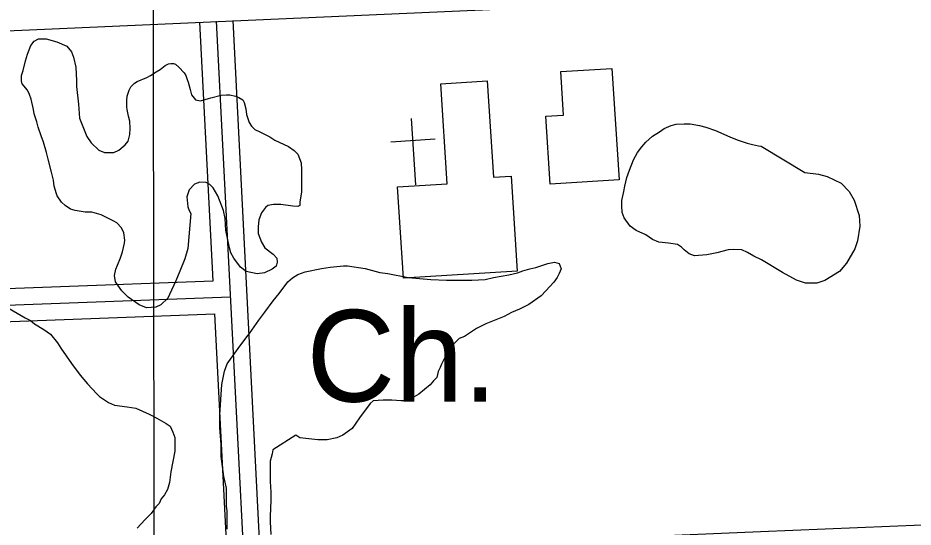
# Model space of a CAD drawing. Extents: x 3313442 to 3351311, y 721974 to 747360.
# Drawn here: x 3333194 to 3334005, y 732187 to 732648 of the extents above; entities that cross this region are included whole.
import ezdxf

# ---------------------------------------------------------------- set-up
doc = ezdxf.new("R2010")
doc.units = 0
for name, color, linetype in [('V-BLDG-OTLN', 7, 'Continuous'), ('V-GRID-MAJR', 7, 'Continuous'), ('V-ROAD-CNTR', 7, 'Continuous'), ('V-SITE-OTLN', 7, 'Continuous'), ('V-SITE-OTLN-IDEN', 7, 'Continuous'), ('V-SITE-VEGE', 7, 'Continuous')]:
    doc.layers.add(name, color=color, linetype=linetype)

msp = doc.modelspace()

# ---------------------------------------------------------------- linework, layer by layer
at = {"layer": 'V-BLDG-OTLN'}
for points in [[(3333731.8, 732602.58), (3333738.19, 732501.68), (3333675.78, 732497.73), (3333671.89, 732559.28), (3333687.97, 732560.29), (3333685.48, 732599.65)], [(3333618.92, 732591.21), (3333624.4, 732504.01), (3333640.54, 732505.03), (3333645.95, 732418.87), (3333542.89, 732412.4), (3333537.69, 732495.23), (3333582.65, 732498.05), (3333576.96, 732588.58)]]:
    msp.add_lwpolyline(points, close=True, dxfattribs=at)
at = {"layer": 'V-GRID-MAJR'}
msp.add_spline([(3333324.14, 727373.91), (3333315.33, 733432.2), (3333306.52, 739493.96), (3333297.7, 745555.74), (3333297.69, 745559.18)], degree=3, dxfattribs=at)
at = {"layer": 'V-ROAD-CNTR'}
for points in [[(3330605.76, 732522.87), (3334476.01, 732693.97), (3336331.78, 732776)], [(3333370.67, 732410.17), (3333358.69, 732644.47)], [(3333449.63, 731159.87), (3333373.67, 732645.24)], [(3333413.32, 732163.72), (3333388.65, 732646)], [(3332752.33, 732386.96), (3332784.63, 732388.3), (3333370.67, 732410.17)], [(3330726.94, 732287.9), (3332785.22, 732373.32), (3333386.43, 732395.75)], [(3332753.74, 732357), (3332785.82, 732358.33), (3333372.21, 732380.21)], [(3333383.34, 732162.43), (3333372.21, 732380.21)], [(3333413.32, 732163.72), (3333866.36, 732183.07), (3334042.13, 732190.17)]]:
    msp.add_lwpolyline(points, dxfattribs=at)
at = {"layer": 'V-SITE-OTLN'}
for p, q in [((3333554.14, 732497.19), (3333550.38, 732557.08)), ((3333571.59, 732538.37), (3333531.67, 732535.86))]:
    msp.add_line(p, q, dxfattribs=at)
at = {"layer": 'V-SITE-VEGE'}
for points in [[(3333347.62, 732439.36), (3333344.86, 732430.02), (3333340.45, 732418.75), (3333336.86, 732410.24), (3333331.08, 732397.6), (3333329.7, 732394.3), (3333323.37, 732388.26), (3333318.69, 732386.34), (3333310.17, 732385.53), (3333303.58, 732388.29), (3333293.69, 732395.45), (3333287.92, 732400.95), (3333282.16, 732409.2), (3333281.34, 732414.98), (3333282.45, 732420.75), (3333284.1, 732424.32), (3333286.58, 732430.92), (3333288.52, 732436.41), (3333290.45, 732444.11), (3333290.73, 732446.85), (3333289.64, 732453.45), (3333287.72, 732458.13), (3333283.32, 732462.53), (3333280.03, 732464.46), (3333273.98, 732467.49), (3333269.31, 732469.97), (3333260.79, 732472.18), (3333254.75, 732472.46), (3333245.68, 732473.85), (3333241.55, 732474.95), (3333236.61, 732478.26), (3333233.31, 732481.29), (3333229.47, 732487.06), (3333228.65, 732488.99), (3333226.73, 732495.86), (3333225.92, 732501.36), (3333224.27, 732508.51), (3333221.27, 732520.33), (3333219.62, 732526.38), (3333216.89, 732535.73), (3333214.97, 732541.51), (3333212.23, 732549.21), (3333210.86, 732554.16), (3333208.4, 732561.31), (3333207.85, 732565.43), (3333205.66, 732574.78), (3333204.29, 732578.91), (3333202.37, 732582.76), (3333197.71, 732588.54), (3333197.16, 732591.28), (3333197.17, 732596.23), (3333198.55, 732600.63), (3333200.76, 732609.43), (3333202.41, 732615.47), (3333205.45, 732623.17), (3333208.48, 732627.28), (3333212.33, 732629.2), (3333219.47, 732629.19), (3333229.09, 732626.71), (3333238.16, 732622.58), (3333242.27, 732617.62), (3333244.19, 732612.67), (3333246.38, 732603.6), (3333246.92, 732591.22), (3333246.91, 732586), (3333248.54, 732570.06), (3333249.62, 732557.41), (3333251.27, 732553.01), (3333256.2, 732540.91), (3333260.04, 732535.13)], [(3333260.04, 732535.13), (3333267.18, 732528.53), (3333272.13, 732526.32), (3333280.65, 732526.31), (3333285.05, 732528.5), (3333290.83, 732533.17), (3333293.58, 732536.74), (3333295.24, 732542.79), (3333295.52, 732548.01), (3333295.25, 732554.88), (3333293.88, 732559.28), (3333292.79, 732565.33), (3333292.52, 732567.81), (3333292.53, 732573.58), (3333292.81, 732577.43), (3333294.46, 732582.92), (3333296.12, 732585.94), (3333299.42, 732589.24), (3333301.89, 732590.61), (3333310.42, 732594.17), (3333314, 732596.09), (3333318.95, 732599.39), (3333322.53, 732601.58), (3333327.2, 732605.15), (3333330.23, 732606.52), (3333332.43, 732607.07), (3333334.62, 732607.06), (3333336.55, 732606.51), (3333339.57, 732603.76), (3333344.24, 732598.53), (3333345.89, 732596.06), (3333346.98, 732592.48), (3333348.08, 732590), (3333349.71, 732583.41), (3333351.09, 732578.73), (3333354.66, 732574.05), (3333359.05, 732573.22), (3333366.47, 732575.14), (3333368.4, 732575.96), (3333377.75, 732578.15), (3333382.7, 732578.69), (3333385.72, 732578.69), (3333390.95, 732577.31), (3333393.97, 732576.2), (3333397.54, 732574), (3333398.64, 732571.52), (3333400.28, 732566.03), (3333400.82, 732560.8), (3333403.29, 732553.65), (3333405.21, 732550.08), (3333408.23, 732547.05), (3333412.9, 732545.12), (3333421.96, 732540.43), (3333426.63, 732537.68), (3333439, 732531.89), (3333443.94, 732528.04), (3333447.23, 732524.74), (3333450.25, 732517.03), (3333450.52, 732510.71), (3333450.49, 732490.65), (3333449.11, 732481.3), (3333449.1, 732478.28), (3333447.18, 732477.45), (3333442.78, 732477.73), (3333432.06, 732479.12), (3333425.19, 732479.13), (3333420.24, 732478.31), (3333418.04, 732476.66), (3333414.46, 732471.72), (3333411.98, 732465.4), (3333411.42, 732459.08), (3333411.41, 732453.03), (3333414.43, 732445.05), (3333417.44, 732440.1), (3333424.86, 732434.32), (3333428.43, 732430.74), (3333428.7, 732427.17), (3333427.59, 732423.32), (3333424.02, 732420.58), (3333417.14, 732417.29), (3333410.54, 732416.47), (3333400.65, 732418.68), (3333395.43, 732422.54), (3333389.39, 732430.52), (3333386.65, 732435.47), (3333385.28, 732440.14), (3333382, 732456.09), (3333381.46, 732466.54), (3333380.1, 732473.96), (3333374.89, 732487.16), (3333370.78, 732494.32), (3333367.48, 732497.34), (3333364.19, 732499.27), (3333358.41, 732499.55), (3333353.74, 732497.63), (3333348.78, 732492.42), (3333346.85, 732486.1), (3333347.67, 732477.02), (3333349.04, 732473.72), (3333350.41, 732471.25), (3333347.62, 732439.36)], [(3333383.23, 732185.29), (3333383.25, 732201.72), (3333382.65, 732205.98), (3333382.67, 732222.4), (3333380.25, 732232.75), (3333377.84, 732251), (3333377.85, 732261.95), (3333376.65, 732277.16), (3333376.67, 732288.72), (3333378.52, 732316.1), (3333380.97, 732328.26), (3333383.42, 732334.95), (3333393.16, 732348.93), (3333401.08, 732359.26), (3333403.52, 732362.3), (3333412.05, 732374.46), (3333417.54, 732381.75), (3333424.85, 732392.09), (3333430.33, 732398.77), (3333438.26, 732409.11), (3333442.52, 732412.75), (3333447.39, 732415.79), (3333454.08, 732418.21), (3333468.69, 732421.24), (3333476.6, 732422.44), (3333488.77, 732423.64), (3333492.42, 732423.64), (3333508.23, 732421.19), (3333521.61, 732417.52), (3333528.91, 732416.9), (3333547.16, 732413.23), (3333567.84, 732411.38), (3333581.83, 732410.76), (3333604.95, 732410.73), (3333617.12, 732411.32), (3333624.42, 732413.14), (3333638.42, 732415.56), (3333646.33, 732417.37), (3333651.2, 732419.19), (3333657.29, 732421.01), (3333662.76, 732422.22), (3333673.72, 732425.85), (3333679.8, 732427.06), (3333684.06, 732425.84), (3333685.88, 732420.97), (3333684.05, 732416.72), (3333682.22, 732413.07), (3333679.17, 732408.82), (3333671.86, 732400.91), (3333667.6, 732396.66), (3333656.64, 732388.77), (3333648.12, 732384.52), (3333640.81, 732381.48), (3333634.12, 732377.84), (3333617.68, 732371.17), (3333609.16, 732366.92), (3333598.2, 732359.63), (3333593.33, 732357.81), (3333587.85, 732352.34), (3333584.8, 732346.87), (3333580.53, 732340.8), (3333577.48, 732334.71), (3333576.27, 732331.68), (3333574.43, 732328.03), (3333573.21, 732322.55), (3333570.17, 732319.52), (3333567.12, 732315.87), (3333556.77, 732307.36), (3333550.68, 732303.72), (3333544.59, 732301.3), (3333540.94, 732301.3), (3333532.43, 732301.92), (3333524.52, 732301.93), (3333515.39, 732301.33), (3333512.95, 732298.9), (3333503.2, 732286.14), (3333496.5, 732276.41)], [(3333185.75, 732385.07), (3333200.35, 732376.54), (3333205.21, 732374.1), (3333208.85, 732371.05), (3333217.37, 732366.18), (3333223.44, 732361.91), (3333229.52, 732354), (3333232.55, 732349.12), (3333242.27, 732335.12), (3333250.17, 732324.77), (3333256.85, 732316.85), (3333265.36, 732307.71), (3333267.79, 732305.28), (3333275.69, 732299.79), (3333281.16, 732297.35), (3333292.72, 732296.12), (3333300.63, 732294.9), (3333312.79, 732289.41), (3333319.47, 732285.75), (3333327.99, 732280.87), (3333331.63, 732278.43), (3333334.06, 732272.95), (3333335.88, 732268.09), (3333335.86, 732255.92), (3333332.19, 732237.06), (3333330.96, 732227.33), (3333329.13, 732221.25), (3333326.69, 732216.39), (3333323.65, 732212.74), (3333321.81, 732208.48), (3333318.77, 732205.44), (3333314.5, 732199.37), (3333309.02, 732193.9), (3333301.71, 732186)], [(3333496.5, 732276.41), (3333487.98, 732270.33), (3333482.5, 732267.91), (3333473.98, 732266.09)], [(3333473.98, 732266.09), (3333465.46, 732266.11), (3333449.04, 732267.95), (3333445.39, 732270.38), (3333424.69, 732257.03), (3333424.08, 732253.38), (3333422.24, 732246.69), (3333422.22, 732228.44), (3333422.82, 732218.7), (3333422.81, 732211.4), (3333422.18, 732196.8), (3333422.18, 732191.94), (3333422.77, 732180.38)]]:
    msp.add_lwpolyline(points, dxfattribs=at)
msp.add_lwpolyline([(3333906.52, 732508.37), (3333918.97, 732506.68), (3333926.7, 732504.65), (3333939.48, 732498.58), (3333946.54, 732491.17), (3333951.23, 732483.09), (3333955.59, 732469.29), (3333956.25, 732459.53), (3333954.22, 732446.41), (3333951.86, 732439.01), (3333944.1, 732426.23), (3333938.04, 732418.51), (3333924.57, 732410.45), (3333917.5, 732408.1), (3333907.07, 732408.11), (3333899, 732410.81), (3333886.22, 732417.56), (3333867.4, 732429.02), (3333860.33, 732432.39), (3333854.62, 732435.76), (3333849.57, 732438.13), (3333841.84, 732438.47), (3333837.13, 732438.14), (3333826.69, 732435.46), (3333817.61, 732433.79), (3333806.5, 732432.8), (3333801.79, 732434.48), (3333797.09, 732438.19), (3333794.74, 732440.55), (3333791.04, 732442.91), (3333782.96, 732444.26), (3333774.22, 732445.28), (3333768.5, 732447.65), (3333762.45, 732451.69), (3333753.71, 732455.74), (3333748.33, 732459.78), (3333742.96, 732467.19), (3333740.94, 732471.9), (3333740.62, 732478.29), (3333740.62, 732483), (3333742.65, 732491.08), (3333743.33, 732495.79), (3333745.36, 732503.86), (3333747.72, 732510.25), (3333751.43, 732519.67), (3333754.8, 732526.39), (3333758.85, 732531.43), (3333762.55, 732535.8), (3333768.62, 732541.18), (3333775.01, 732545.2), (3333779.05, 732548.23), (3333785.45, 732550.91), (3333789.82, 732551.92), (3333797.23, 732552.24), (3333802.61, 732552.24), (3333811.02, 732550.88), (3333816.73, 732549.19), (3333825.48, 732546.15), (3333838.59, 732540.42), (3333845.32, 732537.72), (3333854.4, 732534.68), (3333859.11, 732533.67), (3333864.49, 732532.31), (3333866.85, 732531.97)], close=True, dxfattribs=at)

# ---------------------------------------------------------------- texts
at = {"layer": 'V-SITE-OTLN-IDEN'}
msp.add_text('Ch.', height=83, dxfattribs=at).set_placement((3333455.2, 732300.71))

doc.saveas('drawing.dxf')
